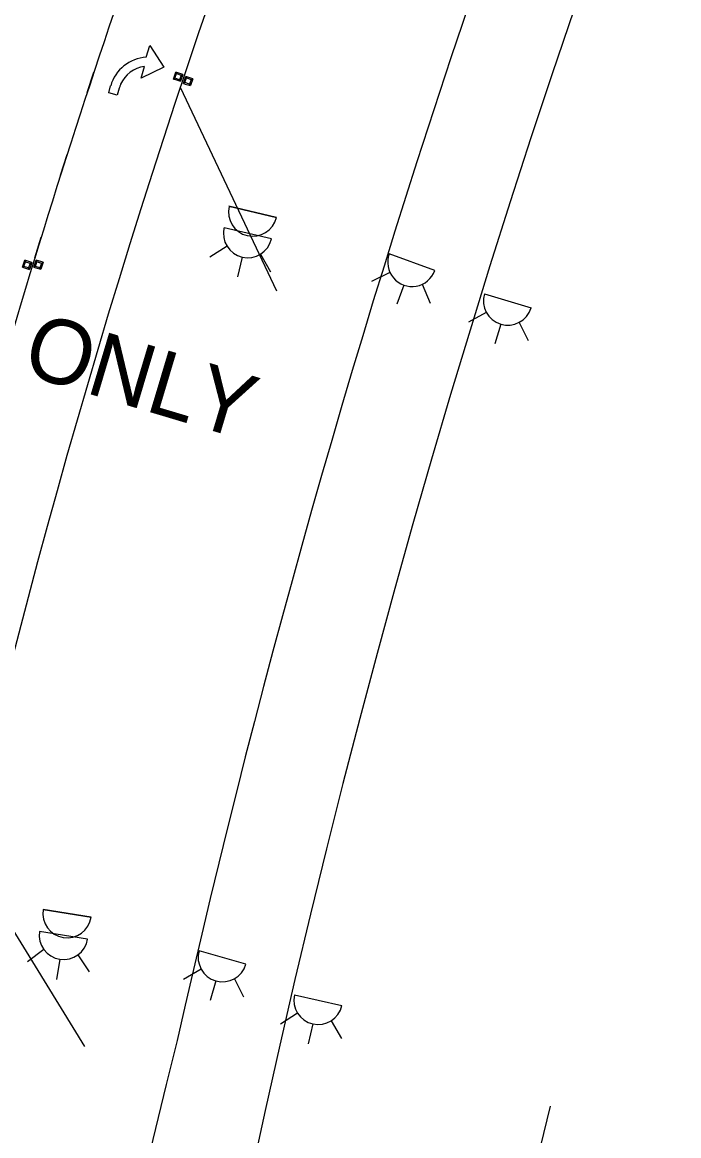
# Model space of a CAD drawing. Extents: x 2471014 to 2497726, y 6959577 to 6980268.
# Drawn here: x 2488516.2 to 2488607.1, y 6963810.8 to 6963964.9 of the extents above; entities that cross this region are included whole.
import ezdxf

# ---------------------------------------------------------------- set-up
doc = ezdxf.new("R2010")
doc.units = 0
for name, color, linetype in [('13', 7, 'Continuous'), ('18', 7, 'Continuous'), ('23', 7, 'Continuous'), ('59', 7, 'Continuous'), ('C-COMM-IDEN', 7, 'Continuous'), ('G-GRID-MAJR', 7, 'Continuous'), ('Level 30', 7, 'Continuous'), ('Level 40', 7, 'Continuous'), ('p_structure fence', 7, 'Continuous'), ('p_structure wall', 7, 'Continuous'), ('PMK_Del_D-SY_SZ_TYC_CTB', 7, 'Continuous'), ('S-BRDG-DECK', 7, 'Continuous'), ('V7_25', 7, 'Continuous')]:
    doc.layers.add(name, color=color, linetype=linetype)

msp = doc.modelspace()

# ---------------------------------------------------------------- linework, layer by layer
at = {"layer": '13'}
msp.add_line((2488564.83, 6963714.6), (2488589.28, 6963814.85), dxfattribs=at)
for centre, radius, start, end in [((2489874.44, 6963535.43), 1450, 149.83805, 187.72757), ((2489916.91, 6963512.7), 1414, 154.2029, 167.28421), ((2489908.57, 6963477.79), 1414, 165.82987, 182.03801)]:
    msp.add_arc(centre, radius, start, end, dxfattribs=at)
at = {"layer": '18'}
for centre, radius, start, end in [((2489916.91, 6963512.7), 1400, 142.23979, 191.359), ((2489874.44, 6963535.43), 1496.5, 149.76396, 167.18435), ((2489874.44, 6963535.43), 1482.5, 149.76396, 167.18435), ((2489663.45, 6963581.69), 1186, 151.87874, 167.63271)]:
    msp.add_arc(centre, radius, start, end, dxfattribs=at)
at = {"layer": '23'}
for p, q in [((2488537.09, 6963957.03), (2488537.42, 6963958)), ((2488538.38, 6963957.67), (2488537.42, 6963958)), ((2488537.42, 6963958), (2488537.51, 6963957.78)), ((2488537.51, 6963957.78), (2488537.65, 6963957.74)), ((2488537.65, 6963957.74), (2488538.15, 6963957.57)), ((2488538.38, 6963957.67), (2488538.05, 6963956.71)), ((2488538.15, 6963957.57), (2488538.38, 6963957.67)), ((2488537.3, 6963957.14), (2488537.09, 6963957.03)), ((2488537.09, 6963957.03), (2488537.35, 6963956.95)), ((2488537.94, 6963956.93), (2488537.3, 6963957.14)), ((2488537.35, 6963956.95), (2488538.05, 6963956.71)), ((2488538.05, 6963956.71), (2488537.94, 6963956.93)), ((2488538.47, 6963956.43), (2488538.79, 6963957.39)), ((2488538.68, 6963956.53), (2488538.47, 6963956.43)), ((2488538.47, 6963956.43), (2488538.73, 6963956.34)), ((2488539.32, 6963956.32), (2488538.68, 6963956.53)), ((2488538.73, 6963956.34), (2488539.43, 6963956.11)), ((2488539.75, 6963957.07), (2488538.79, 6963957.39)), ((2488538.79, 6963957.39), (2488538.89, 6963957.18)), ((2488538.89, 6963957.18), (2488539.02, 6963957.13)), ((2488539.02, 6963957.13), (2488539.53, 6963956.96)), ((2488539.43, 6963956.11), (2488539.32, 6963956.32)), ((2488539.75, 6963957.07), (2488539.43, 6963956.11)), ((2488539.53, 6963956.96), (2488539.75, 6963957.07)), ((2488516.19, 6963930.97), (2488516.49, 6963931.94)), ((2488517.46, 6963931.64), (2488516.49, 6963931.94)), ((2488516.49, 6963931.94), (2488516.59, 6963931.73)), ((2488516.59, 6963931.73), (2488516.72, 6963931.69)), ((2488516.72, 6963931.69), (2488517.24, 6963931.53)), ((2488517.46, 6963931.64), (2488517.16, 6963930.67)), ((2488517.24, 6963931.53), (2488517.46, 6963931.64)), ((2488517.77, 6963930.99), (2488518.06, 6963931.96)), ((2488519.03, 6963931.66), (2488518.06, 6963931.96)), ((2488518.06, 6963931.96), (2488518.16, 6963931.75)), ((2488518.16, 6963931.75), (2488518.3, 6963931.71)), ((2488518.3, 6963931.71), (2488518.81, 6963931.55)), ((2488519.03, 6963931.66), (2488518.73, 6963930.69)), ((2488518.81, 6963931.55), (2488519.03, 6963931.66)), ((2488516.39, 6963931.08), (2488516.19, 6963930.97)), ((2488516.19, 6963930.97), (2488516.45, 6963930.89)), ((2488517.04, 6963930.88), (2488516.39, 6963931.08)), ((2488516.45, 6963930.89), (2488517.16, 6963930.67)), ((2488517.16, 6963930.67), (2488517.04, 6963930.88)), ((2488517.97, 6963931.1), (2488517.77, 6963930.99)), ((2488517.77, 6963930.99), (2488518.02, 6963930.91)), ((2488518.61, 6963930.91), (2488517.97, 6963931.1)), ((2488518.02, 6963930.91), (2488518.73, 6963930.69)), ((2488518.73, 6963930.69), (2488518.61, 6963930.91))]:
    msp.add_line(p, q, dxfattribs=at)
for points in [[(2488537.3, 6963957.14), (2488537.51, 6963957.78), (2488538.15, 6963957.57), (2488537.94, 6963956.93)], [(2488538.68, 6963956.53), (2488538.89, 6963957.18), (2488539.53, 6963956.96), (2488539.32, 6963956.32)], [(2488516.39, 6963931.08), (2488516.59, 6963931.73), (2488517.24, 6963931.53), (2488517.04, 6963930.88)], [(2488517.97, 6963931.1), (2488518.16, 6963931.75), (2488518.81, 6963931.55), (2488518.61, 6963930.91)]]:
    msp.add_lwpolyline(points, close=True, dxfattribs=at)
at = {"layer": '59'}
msp.add_arc((2489663.45, 6963581.69), 1198, 161.17883, 167.62962, dxfattribs=at)
at = {"layer": 'C-COMM-IDEN'}
for p, q in [((2488544.78, 6963939.41), (2488551.36, 6963937.87)), ((2488551.36, 6963937.87), (2488544.78, 6963939.41)), ((2488550.66, 6963934.89), (2488544.09, 6963936.43)), ((2488544.51, 6963933.88), (2488542.14, 6963932.36)), ((2488546.61, 6963932.38), (2488545.96, 6963929.64)), ((2488549.15, 6963932.79), (2488550.55, 6963930.35)), ((2488519.03, 6963842.08), (2488525.69, 6963841.02)), ((2488525.69, 6963841.02), (2488519.03, 6963842.08)), ((2488525.21, 6963838), (2488518.55, 6963839.06)), ((2488519.15, 6963836.55), (2488516.9, 6963834.86)), ((2488521.35, 6963835.2), (2488520.91, 6963832.42)), ((2488523.86, 6963835.8), (2488525.43, 6963833.46))]:
    msp.add_line(p, q, dxfattribs=at)
for centre, start, end in [((2488548.07, 6963938.64), 166.8304, 346.8304), ((2488547.37, 6963935.66), 166.8304, 346.8304), ((2488522.36, 6963841.55), 170.9822, 350.9822), ((2488521.88, 6963838.53), 170.9822, 350.9822)]:
    msp.add_arc(centre, 3.37, start, end, dxfattribs=at)
at = {"layer": 'G-GRID-MAJR'}
for p, q in [((2488538.02, 6963955.88), (2488551.37, 6963927.73)), ((2488508.21, 6963850.04), (2488524.75, 6963823.11))]:
    msp.add_line(p, q, dxfattribs=at)
at = {"layer": 'Level 30'}
for p, q in [((2488580.15, 6963927.31), (2488586.61, 6963925.35)), ((2488580.4, 6963924.73), (2488577.94, 6963923.37)), ((2488582.4, 6963923.1), (2488581.58, 6963920.4)), ((2488584.97, 6963923.35), (2488586.2, 6963920.82)), ((2488553.84, 6963830.29), (2488560.42, 6963828.8)), ((2488554.27, 6963827.74), (2488551.92, 6963826.21)), ((2488558.93, 6963826.69), (2488560.34, 6963824.25)), ((2488556.38, 6963826.25), (2488555.76, 6963823.51))]:
    msp.add_line(p, q, dxfattribs=at)
for centre, start, end in [((2488583.38, 6963926.33), 163.1237, 343.1237), ((2488557.13, 6963829.54), 167.2397, 347.2397)]:
    msp.add_arc(centre, 3.37, start, end, dxfattribs=at)
at = {"layer": 'Level 40'}
for p, q in [((2488525.15, 6963955.15), (2488526.08, 6963958)), ((2488521.46, 6963943.73), (2488522.37, 6963946.59)), ((2488517.89, 6963932.27), (2488518.77, 6963935.14))]:
    msp.add_line(p, q, dxfattribs=at)
at = {"layer": 'p_structure wall'}
for p, q in [((2488533.33, 6963960.04), (2488533.81, 6963961.69)), ((2488533.81, 6963961.69), (2488535.75, 6963958.66)), ((2488532.6, 6963957.17), (2488533.06, 6963958.78)), ((2488535.75, 6963958.66), (2488532.6, 6963957.17)), ((2488528.12, 6963955.14), (2488528.39, 6963956.09)), ((2488529.3, 6963954.8), (2488528.12, 6963955.14)), ((2488529.58, 6963955.75), (2488529.3, 6963954.8))]:
    msp.add_line(p, q, dxfattribs=at)
for radius, start, end in [(5.49, 93.5336, 163.823), (4.26, 98.2092, 155.9518), (4.26, 158.1992, 163.782), (4.26, 155.9518, 158.1992)]:
    msp.add_arc((2488533.67, 6963954.56), radius, start, end, dxfattribs=at)
at = {"layer": 'PMK_Del_D-SY_SZ_TYC_CTB'}
for p, q in [((2488573.29, 6963930.52), (2488566.95, 6963932.83)), ((2488567.06, 6963930.25), (2488564.53, 6963929.02)), ((2488568.97, 6963928.5), (2488568.01, 6963925.86)), ((2488571.55, 6963928.62), (2488572.64, 6963926.03)), ((2488547.13, 6963834.54), (2488540.63, 6963836.39)), ((2488540.93, 6963833.82), (2488538.49, 6963832.42)), ((2488542.96, 6963832.22), (2488542.19, 6963829.51)), ((2488545.52, 6963832.51), (2488546.79, 6963830))]:
    msp.add_line(p, q, dxfattribs=at)
for centre, start, end in [((2488570.12, 6963931.68), 160.0443, 340.0443), ((2488543.88, 6963835.46), 164.0963, 344.0963)]:
    msp.add_arc(centre, 3.37, start, end, dxfattribs=at)
at = {"layer": 'S-BRDG-DECK'}
msp.add_arc((2489874.44, 6963535.43), 1482.5, 149.43453, 167.18435, dxfattribs=at)
at = {"layer": 'V7_25'}
for radius in [1438, 1426]:
    msp.add_arc((2489874.44, 6963535.43), radius, 149.83805, 187.72757, dxfattribs=at)

# ---------------------------------------------------------------- texts
at = {"layer": 'p_structure fence'}
msp.add_text('ONLY', height=8.898, rotation=343.3226, dxfattribs=at).set_placement((2488515.83, 6963916.32))

doc.saveas('drawing.dxf')
